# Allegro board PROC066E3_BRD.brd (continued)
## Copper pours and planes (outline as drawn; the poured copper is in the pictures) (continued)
2_VCC_1V8 on TOP: 74.04,29.01 77.11,29.01 77.11,27.74 74.04,27.74
2_VCC_1V8 on TOP: 69.2,29.01 70.72,29.01 70.72,27.74 69.2,27.74
2_VCC_3V3 on TOP (solid shape): 24.77,26.18 18.27,26.18 17.89,26.56 17.89,34.06 20.23,36.4 24.77,36.4
2_VCC_3V3 on L03_PWR: 10.05,40.97 10.05,22.12 25.38,22.12 25.38,40.97
2_VCC_5V on TOP: 91.3,22.33 94.36,22.33 94.36,18.47 89.71,18.47 89.71,22.07 91.3,22.07
2_VCC_5V on TOP: 17.95,3.61 17.95,9.32 20.75,9.32 20.75,3.61
2_VCC_5V on BOTTOM: 17.95,3.73 17.95,9.32 20.62,9.32 20.62,3.73
2_VCC_5V on L03_PWR: 18.52,9.34 24.77,9.34 27.41,6.7 87.18,6.7 87.18,21.84 97.21,21.84 97.21,1.14 15.47,1.14 15.47,8.28 17.45,8.28
2_VCC_5V on L04_SIG1: 18.52,9.34 24.77,9.34 30.23,3.88 85.68,3.88 87.18,5.38 87.18,21.82 97.21,21.82 97.21,1.14 15.47,1.14 15.47,8.28 17.45,8.28
2_VCC_12V on TOP (solid shape): 20.94,20.22 22.78,20.22 22.94,20.06 22.94,16.07 22.45,15.58 22.45,14.01 20.94,12.5 20.94,10.71 20.92,10.62 20.91,10.53 20.91,10.15 20.92,10.06 20.94,9.97 20.94,9.58 18.66,9.58 18.66,9.62 17.88,10.65 16.61,10.4 16.5,10.38 16.44,10.48 16.44,16.12 16.62,16.3 16.62,19.05 16.7,19.13 16.7,20.24 20.94,20.24
2_VCC_12V on L03_PWR: 10.05,9.72 10.05,21.41 23.44,21.41 23.44,12.82 20.34,9.72
2_VCC_FUN_3V3 on TOP: 49.45,2.84 48.94,3.35 48.94,4.88 49.96,4.88 50.21,5.13 50.21,7.8 50.85,7.8 50.85,7.16 51.86,7.16 51.86,4.88 52.12,4.62 54.83,4.62 55.14,4.93 55.14,5.84 55.19,5.89 55.65,5.89 55.7,5.84 55.7,4.9 55.98,4.62 65.58,4.62 66.21,5.26 66.21,8.81 66.47,9.07 69.45,9.07 69.45,7.54 68.88,7.54 68.88,6.65 69.77,5.77 78.53,5.77 78.91,6.15 78.91,8.56 81.07,8.56 81.07,3.61 80.31,2.84
2_VCC_FUN_3V3 on BOTTOM: 42.79,14.99 42.79,14.43 42.69,14.33 42.69,12.17 41.42,12.17 41.42,15.04 42.74,15.04
2_VCC_FUN_3V3 on L03_PWR: 85.73,20.77 85.73,7.34 68.05,7.34 68.05,13.64 69.24,14.83 69.24,20.77
2_VCC_PCIE_3V3 on TOP: 25.53,38.99 25.53,33.15 31.75,33.15 31.75,38.99
2_VCC_PCIE_3V3 on L03_PWR: 26.01,40.89 57.12,40.89 57.12,32.93 57.13,17.53 55.41,15.8 37.95,15.8 31.6,22.15 26.01,22.15
2_VCC_PCIE_12V on TOP (solid shape): 62.51,27.24 62.03,26.67 61.53,27.21 61.53,27.86 61.71,28.04
2_VCC_PCIE_12V on TOP: 27.3,20.93 27.3,16.26 23.7,16.26 23.7,20.29 24.34,20.93
2_VCC_PCIE_12V on BOTTOM: 67.85,27.2 67.85,23.8 65.36,23.8 65.36,27.2
2_VCC_PCIE_12V on L03_PWR: 24.07,21.39 24.07,12.07 28.81,7.34 67.42,7.34 67.42,14.58 68.25,15.41 68.25,31.7 58.98,31.7 58.98,18.26 55.91,15.19 37.24,15.19 31.04,21.39
USB_SHIELD2 on TOP: 86.59,39.75 86.59,41.33 86.34,41.58 66.55,41.58 66.06,41.09 66.06,38.6 67.8,38.6 68.23,38.17 70.92,38.17 72.72,39.98 82.37,39.98 82.93,39.42 86.26,39.42
USB_SHIELD2 on BOTTOM: 86.59,39.75 86.59,41.33 86.34,41.58 66.55,41.58 66.06,41.09 66.06,38.6 67.8,38.6 68.3,38.1 70.9,38.1 72.78,39.98 82.37,39.98 82.93,39.42 86.26,39.42
USB_SHIELD2 on L02_GND1: 86.59,39.75 86.59,41.33 86.34,41.58 66.55,41.58 66.06,41.09 66.06,38.79 66.25,38.6 67.8,38.6 68.3,38.1 70.79,38.1 72.67,39.98 82.37,39.98 82.93,39.42 86.26,39.42
USB_SHIELD2 on L03_PWR: 86.59,39.75 86.59,41.33 86.34,41.58 66.55,41.58 66.06,41.09 66.06,38.6 67.8,38.6 68.3,38.1 70.97,38.1 72.85,39.98 82.37,39.98 82.93,39.42 86.26,39.42
USB_SHIELD2 on L04_SIG1: 86.59,39.75 86.59,41.33 86.34,41.58 66.55,41.58 66.06,41.09 66.06,38.6 67.8,38.6 68.3,38.1 71,38.1 72.88,39.98 82.37,39.98 82.93,39.42 86.26,39.42
USB_SHIELD2 on L05_GND2: 86.59,39.75 86.59,41.33 86.34,41.58 66.55,41.58 66.06,41.09 66.06,38.6 67.8,38.6 68.3,38.1 70.85,38.1 72.72,39.98 82.37,39.98 82.93,39.42 86.26,39.42
N17014112 on TOP (solid shape): 17.1,24.33 16.81,24.04 16.81,23.98 16.8,23.98 16.8,22.91 16.2,22.91 16.2,24.05 15.6,24.65 15.6,24.96 15.39,25.17 12.19,25.17 12.19,31.67 17.1,31.67
N17014166 on TOP: 18.06,22.2 18.89,22.2 18.89,23.34 21.56,23.34 21.56,24.21 21.51,24.26 18.77,24.26 18.22,23.71 18.22,22.59 18.06,22.43
N17025145 on TOP: 89.01,26.39 89.01,23.98 89.26,23.72 91.93,23.72 91.93,24.87 90.28,24.87 90.03,25.12 90.03,26.39
N17801417 on TOP: 100.66,40.97 100.56,41.07 98,41.07 97.97,41.04 91.59,41.04 91.34,40.79 91.34,35.05 91.69,34.7 91.69,32.38 91.74,32.33 93.62,32.33 97.23,35.94 99.92,35.94 100.66,36.68

Small or netless copper shapes (teardrops, artwork), in the pictures only: 67 on TOP, 21 on BOTTOM, 31 on L04_SIG1

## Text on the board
Ref Des/Assembly Bottom: SER-PCIEUSBEVM_REV.E3_ASSEMBLY DRAWING BOTTOM
Ref Des/Silkscreen Bottom: FOR RESALE | NOT FCC APPROVED | FOR EVALUATION ONLY;
User.Comments: CR_USB_PWR_2 | CR_POWER_2 | CR_ETHERNET_2 | CR_POWER_3 | CR_CLOCK_4 | CR_PFY_2 | CR_CLOCK_3 | CR_DIFF_2 | CR_DIFF_1 | CR_EPROM_4 | CR_EPROM_3 | CR_EROM_4 | CR_EROM_3 | CR_EROM_1 | CR_CLKKKKKKKK_3 | CR_PHY_2 | CR_CLOCK_2 | BOARD NAME: | SER-PCIEUSBEVM | REV: E3 | DATE: 02/07/2018 | DESCRIPTION: | SHEET | OF | 21 | PROC066 | SCALE: 1 | TEXAS INSTRUMENTS
Ref Des/Assembly Top: SER-PCIEUSBEVM_REV.E3_ASSEMBLY DRAWING TOP
Ref Des/Silkscreen Top: ASSM REV : 1.0 | ASSM P/N : 4P0086 | PROC066 | EXT | PCIe x1 | REST | INT | USB 3.0 | HOST_SEL
PAGE_OUTLINE: LAYOUT BY | REVIEWED BY | APPROVED BY | SIGNATURES | CMMR | AMB | ZA | DATE | 020718 | SIZE | SCALE: | D | NONE | SHEET 1 OF 21 | PROC066 | Rev | E3 | REV # | DESCRIPTION | TEXAS INSTRUMENTS | REVISIONS | CCN # | SER-PCIEUSBEVM | DDMMYY
DIMENSION: 10 | 3 | 12 | 8 | 5 | 6 | 48 | 37 | 36 | 25 | 4 | 2 | 1 | A | B | C | D | E | 13 | 24 | 32 | 17 | 16 | 9 | 120 | 60 | 119 | 59 | 15 | 7 | 11 | 20 | 40 | PUSH | MATING | EJECT | 30 | 31 | 19 | B11 | B14 | A14 | A11 | B1 | A10 | B10 | K | 39 | 14
User.11: 14. | ALL NON FUNCTIONAL PAD'S OF VIA'S AND PTH HOLES SHALL BE REMOVED.
User.40: 07 | 05 | 02 | 03 | 06 | 04 | EDGE COUPLED STRIPLINE | EDGE COUPLED MICROSTRIP | L4 | L1,L6 | 4 | 8.2 | 8.8 | 9.2 | 8 | 14 | 5.5 | 5 | 6.2 | 7 | NA | 100 | 90 | 85 | 50 | L2,L5 | L5/L3
User.41: 0.5oz.+PLATING
User.42: FIGURE | SIZE | 8.0 | 28.0 | 40.0 | 44.0 | 46.0 | 32.0 | 42.0 | 56.0 | 92.0 | 108.0 | DRILL CHART: TOP to BOTTOM | ALL UNITS ARE IN MILS | TOLERANCE | +3.0/-4.0 | +3.0/-3.0 | +2.0/-2.0 | PLATED | NON-PLATED | QTY | 452 | 46 | 6 | 3 | 2 | 12 | 9
User.44: 2 | 3 | 5 | 6 | 8 | 4 | 10 | 11 | 12 | 13 | 48 | A10 | 37 | 24 | 60 | 25 | 59 | 32 | 20 | 17 | 16 | 120 | 9 | 119 | 19 | 15 | 7 | 30 | 1 | A | B | C | D | E | 31 | B11 | B14 | A11 | A14 | B1 | 36 | PUSH | MATING | EJECT | B10 | 14 | K | 40 | 39
